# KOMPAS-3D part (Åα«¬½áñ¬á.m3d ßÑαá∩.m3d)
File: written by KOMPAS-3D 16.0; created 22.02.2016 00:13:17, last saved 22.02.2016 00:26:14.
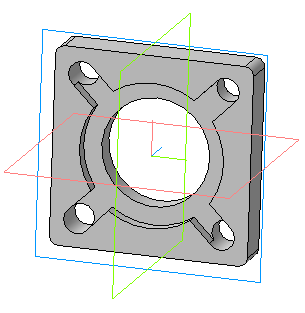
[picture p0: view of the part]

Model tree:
1. Эскиз:1
2. Операция выдавливания:1
     Расстояние 1 = 8
3. Эскиз:2
4. Вырезать элемент выдавливания:1
     Расстояние 1 = 3
5. Скругление:1
     Радиус = 2
6. Скругление:2
     Радиус = 2
7. Скругление:3
     Радиус = 2
8. Скругление:4
     Радиус = 2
